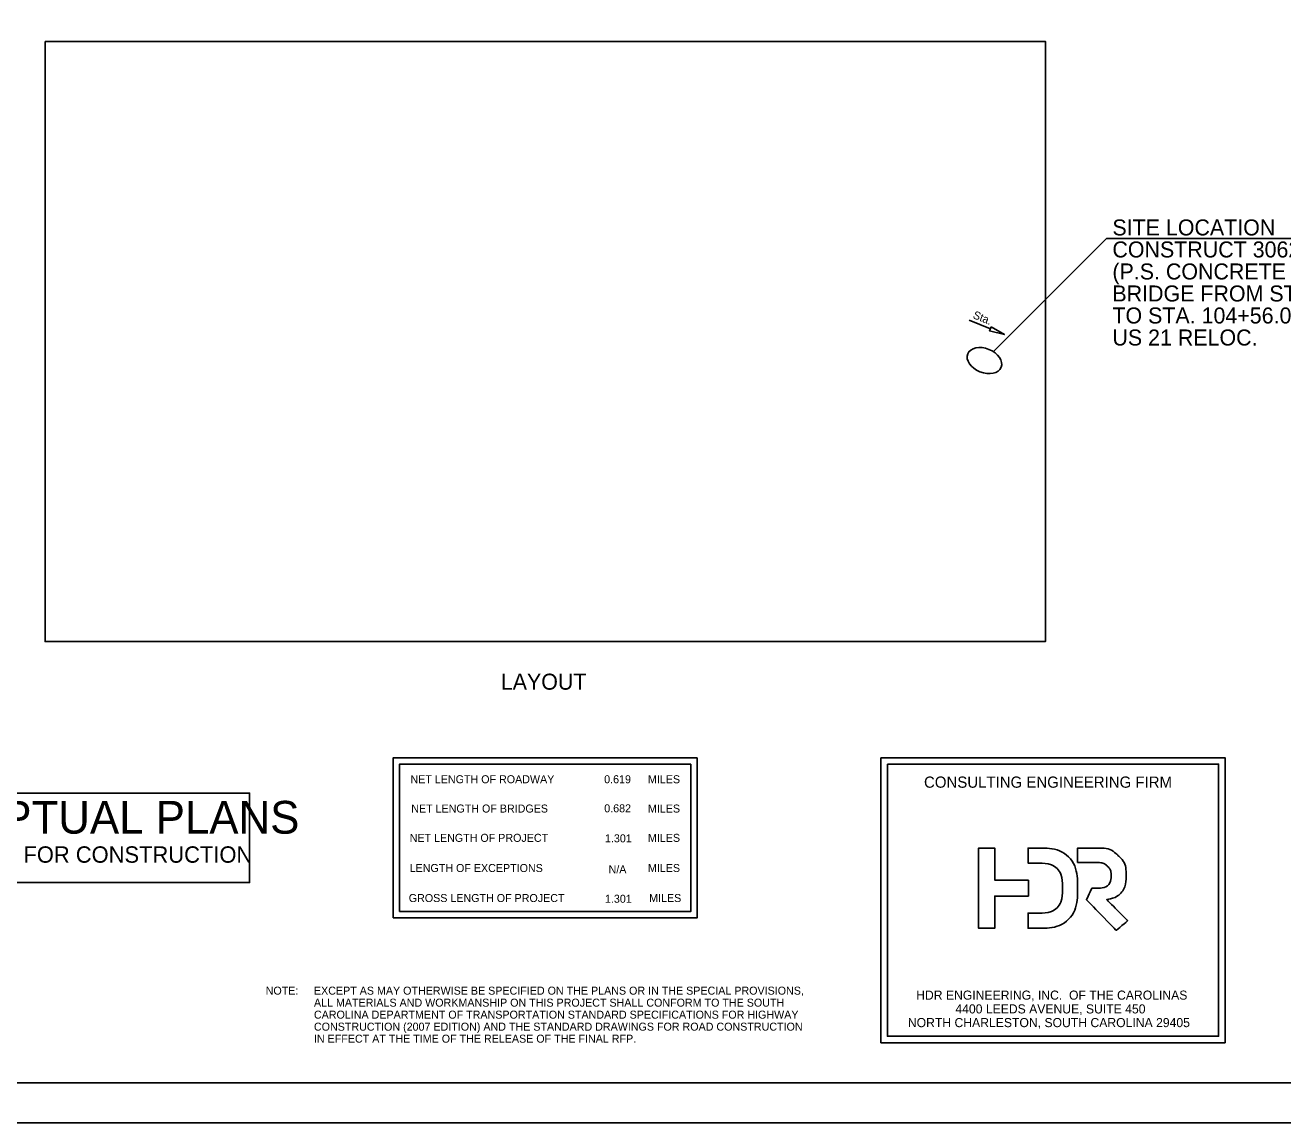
# Model space of a CAD drawing. Extents: x 1034.1 to 1070.1, y 1567.5 to 1589.5.
# Drawn here: x 1046.36 to 1062.08, y 1567.5 to 1581.21 of the extents above; entities that cross this region are included whole.
import ezdxf

# ---------------------------------------------------------------- set-up
doc = ezdxf.new("R2010")
doc.units = 0
for name, color, linetype in [('BR_BORDER LINES', 7, 'Continuous'), ('Level 3', 7, 'Continuous'), ('Plan Sheet CELL', 7, 'Continuous'), ('Sheet Plot Border Outside CELL', 7, 'Continuous'), ('Sheet Sticker Preliminary CELL', 7, 'Continuous')]:
    doc.layers.add(name, color=color, linetype=linetype)

msp = doc.modelspace()

# ---------------------------------------------------------------- linework, layer by layer
at = {"layer": 'BR_BORDER LINES'}
msp.add_line((1036.11, 1567.998), (1069.61, 1567.998), dxfattribs=at)
msp.add_lwpolyline([(1046.61, 1581.008), (1059.11, 1581.008), (1059.11, 1573.508), (1046.61, 1573.508)], close=True, dxfattribs=at)
at = {"layer": 'Level 3'}
for p, q in [((1058.459, 1577.131), (1059.873, 1578.545)), ((1063.958, 1578.545), (1059.873, 1578.545)), ((1058.158, 1577.523), (1058.423, 1577.417))]:
    msp.add_line(p, q, dxfattribs=at)
msp.add_lwpolyline([(1058.434, 1577.443), (1058.598, 1577.347), (1058.413, 1577.391)], close=True, dxfattribs=at)
msp.add_ellipse((1058.348, 1577.02), major_axis=(0.209, -0.084), ratio=0.666667, dxfattribs=at)
at = {"layer": 'Plan Sheet CELL'}
for points in [[(1054.76, 1572.058), (1050.96, 1572.058), (1050.96, 1570.058), (1054.76, 1570.058)], [(1057.055, 1572.058), (1061.355, 1572.058), (1061.355, 1568.498), (1057.055, 1568.498)], [(1054.68, 1571.978), (1051.04, 1571.978), (1051.04, 1570.138), (1054.68, 1570.138)], [(1057.135, 1571.978), (1061.275, 1571.978), (1061.275, 1568.578), (1057.135, 1568.578)]]:
    msp.add_lwpolyline(points, close=True, dxfattribs=at)
for points in [[(1058.898, 1570.529), (1058.898, 1570.529), (1058.477, 1570.529), (1058.477, 1570.529), (1058.477, 1570.529), (1058.477, 1570.529), (1058.477, 1570.929), (1058.477, 1570.929), (1058.477, 1570.929), (1058.477, 1570.929), (1058.274, 1570.929), (1058.274, 1570.929), (1058.274, 1570.929), (1058.274, 1570.929), (1058.274, 1569.928), (1058.274, 1569.928), (1058.274, 1569.928), (1058.274, 1569.928), (1058.477, 1569.928), (1058.477, 1569.928), (1058.477, 1569.928), (1058.477, 1569.928), (1058.477, 1570.329), (1058.477, 1570.329), (1058.477, 1570.329), (1058.477, 1570.329), (1058.898, 1570.329), (1058.898, 1570.329), (1058.898, 1570.329), (1058.898, 1570.329), (1058.898, 1570.529), (1058.898, 1570.529)], [(1059.512, 1570.429), (1059.512, 1570.429), (1059.512, 1570.43), (1059.512, 1570.43), (1059.512, 1570.43), (1059.512, 1570.43), (1059.512, 1570.43), (1059.512, 1570.43), (1059.512, 1570.43), (1059.511, 1570.719), (1059.301, 1570.929), (1059.011, 1570.929), (1059.011, 1570.929), (1059.011, 1570.929), (1058.893, 1570.929), (1058.893, 1570.929), (1058.893, 1570.929), (1058.893, 1570.929), (1058.893, 1570.741), (1058.893, 1570.741), (1058.893, 1570.741), (1058.893, 1570.741), (1059.011, 1570.741), (1059.011, 1570.741), (1059.011, 1570.741), (1059.195, 1570.741), (1059.324, 1570.613), (1059.324, 1570.429), (1059.324, 1570.429), (1059.324, 1570.245), (1059.195, 1570.116), (1059.011, 1570.116), (1059.011, 1570.116), (1059.011, 1570.116), (1058.893, 1570.116), (1058.893, 1570.116), (1058.893, 1570.116), (1058.893, 1570.116), (1058.893, 1569.928), (1058.893, 1569.928), (1058.893, 1569.928), (1058.893, 1569.928), (1059.011, 1569.928), (1059.011, 1569.928), (1059.011, 1569.928), (1059.301, 1569.928), (1059.511, 1570.139), (1059.512, 1570.429), (1059.512, 1570.429), (1059.512, 1570.429), (1059.512, 1570.429), (1059.512, 1570.429), (1059.512, 1570.429), (1059.512, 1570.429), (1059.512, 1570.429), (1059.512, 1570.429)], [(1059.512, 1570.749), (1059.512, 1570.749), (1059.738, 1570.749), (1059.738, 1570.749), (1059.738, 1570.749), (1059.806, 1570.749), (1059.852, 1570.735), (1059.885, 1570.702), (1059.885, 1570.702), (1059.916, 1570.672), (1059.931, 1570.633), (1059.931, 1570.588), (1059.931, 1570.588), (1059.931, 1570.487), (1059.844, 1570.427), (1059.747, 1570.427), (1059.747, 1570.427), (1059.747, 1570.427), (1059.69, 1570.427), (1059.69, 1570.427), (1059.69, 1570.427), (1059.69, 1570.427), (1059.624, 1570.284), (1059.624, 1570.284), (1059.624, 1570.284), (1059.624, 1570.284), (1059.994, 1569.9), (1059.994, 1569.9), (1059.994, 1569.9), (1059.994, 1569.9), (1060.138, 1570.021), (1060.138, 1570.021), (1060.138, 1570.021), (1060.138, 1570.021), (1059.876, 1570.286), (1059.876, 1570.286), (1059.876, 1570.286), (1060.02, 1570.313), (1060.119, 1570.445), (1060.119, 1570.584), (1060.119, 1570.584), (1060.119, 1570.689), (1060.089, 1570.769), (1060.015, 1570.839), (1060.015, 1570.839), (1059.938, 1570.912), (1059.852, 1570.929), (1059.724, 1570.929), (1059.724, 1570.929), (1059.724, 1570.929), (1059.512, 1570.929), (1059.512, 1570.929), (1059.512, 1570.929), (1059.512, 1570.929), (1059.512, 1570.749), (1059.512, 1570.749)]]:
    msp.add_open_spline(points, degree=3, dxfattribs=at)
at = {"layer": 'Sheet Plot Border Outside CELL'}
msp.add_lwpolyline([(1034.11, 1589.496), (1070.11, 1589.496), (1070.11, 1567.496), (1034.11, 1567.496)], close=True, dxfattribs=at)
at = {"layer": 'Sheet Sticker Preliminary CELL'}
msp.add_lwpolyline([(1043.672, 1570.498), (1043.672, 1571.617), (1049.164, 1571.617), (1049.164, 1570.498)], close=True, dxfattribs=at)

# ---------------------------------------------------------------- texts
at = {"layer": 'Level 3'}
for s, height, p in [(' SITE LOCATION', 0.2, (1059.873, 1578.583)), (' CONSTRUCT 3062\'-0"', 0.2, (1059.873, 1578.308)), (' (P.S. CONCRETE BEAM)', 0.2, (1059.873, 1578.033)), (' BRIDGE FROM STA. 68+54.00', 0.2, (1059.873, 1577.758)), (' TO STA. 104+56.00 ALONG C', 0.2, (1059.873, 1577.483)), (' US 21 RELOC.', 0.2, (1059.873, 1577.208)), ('LAYOUT', 0.2, (1052.304, 1572.908)), ('NOTE:', 0.1, (1049.366, 1569.098)), ('EXCEPT AS MAY OTHERWISE BE SPECIFIED ON THE PLANS OR IN THE SPECIAL PROVISIONS,', 0.1, (1049.969, 1569.098)), ('ALL MATERIALS AND WORKMANSHIP ON THIS PROJECT SHALL CONFORM TO THE SOUTH', 0.1, (1049.969, 1568.948)), ('CAROLINA DEPARTMENT OF TRANSPORTATION STANDARD SPECIFICATIONS FOR HIGHWAY', 0.1, (1049.969, 1568.798)), ('CONSTRUCTION (2007 EDITION) AND THE STANDARD DRAWINGS FOR ROAD CONSTRUCTION', 0.1, (1049.969, 1568.648)), ('IN EFFECT AT THE TIME OF THE RELEASE OF THE FINAL RFP.', 0.1, (1049.969, 1568.498))]:
    msp.add_text(s, height=height, dxfattribs=at).set_placement(p)
msp.add_text('Sta.', height=0.1, rotation=338.2754, dxfattribs=at).set_placement((1058.196, 1577.552))
at = {"layer": 'Plan Sheet CELL'}
for s, height, p in [('NET LENGTH OF ROADWAY', 0.1, (1051.175, 1571.739)), ('0.619', 0.1, (1053.596, 1571.739)), ('MILES', 0.1, (1054.143, 1571.739)), ('CONSULTING ENGINEERING FIRM', 0.14, (1057.593, 1571.683)), ('NET LENGTH OF BRIDGES', 0.1, (1051.185, 1571.373)), ('0.682', 0.1, (1053.597, 1571.376)), ('MILES', 0.1, (1054.143, 1571.373)), ('NET LENGTH OF PROJECT', 0.1, (1051.165, 1571.007)), ('MILES', 0.1, (1054.143, 1571.007)), ('1.301', 0.1, (1053.606, 1571.001)), ('LENGTH OF EXCEPTIONS', 0.1, (1051.165, 1570.63)), ('N/A', 0.1, (1053.651, 1570.614)), ('MILES', 0.1, (1054.143, 1570.63)), ('GROSS LENGTH OF PROJECT', 0.1, (1051.154, 1570.255)), ('1.301', 0.1, (1053.606, 1570.246)), ('MILES', 0.1, (1054.158, 1570.255)), ('HDR ENGINEERING, INC.  OF THE CAROLINAS', 0.11376, (1057.495, 1569.035)), ('4400 LEEDS AVENUE, SUITE 450', 0.11376, (1057.985, 1568.863)), ('NORTH CHARLESTON, SOUTH CAROLINA 29405', 0.11376, (1057.391, 1568.692))]:
    msp.add_text(s, height=height, dxfattribs=at).set_placement(p)
at = {"layer": 'Sheet Sticker Preliminary CELL'}
for s, height, p in [('CONCEPTUAL PLANS', 0.40949, (1044.097, 1571.109)), ('DO NOT USE FOR CONSTRUCTION', 0.20475, (1044.559, 1570.746))]:
    msp.add_text(s, height=height, rotation=360, dxfattribs=at).set_placement(p)

doc.saveas('drawing.dxf')
